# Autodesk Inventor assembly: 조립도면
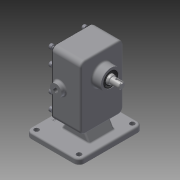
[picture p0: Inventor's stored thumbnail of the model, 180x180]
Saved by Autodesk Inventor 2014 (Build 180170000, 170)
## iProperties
Created: 2020-04
Part Number: 조립도면
Document SubType Name: Assembly
Designer: kh
Author: kh
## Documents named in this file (11)
- C:\Users\kh\Desktop\700407V1020\조립도면.iam
- C:\Users\kh\Desktop\700407V1020\본체.ipt
- C:\Users\kh\Desktop\700407V1020\개스킷.ipt
- C:\Users\kh\Desktop\700407V1020\메인축.ipt
- C:\Users\kh\Desktop\700407V1020\베어링부시.ipt
- C:\Users\kh\Desktop\700407V1020\볼트 M5.ipt
- C:\Users\kh\Desktop\700407V1020\서브축.ipt
- C:\Users\kh\Desktop\700407V1020\스퍼기어.ipt
- C:\Users\kh\Desktop\700407V1020\오일 실 16 28 7.ipt
- C:\Users\kh\Desktop\700407V1020\커버.ipt
- C:\Users\kh\Desktop\700407V1020\키 6 x 6 x 18.ipt
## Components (1 placed, 1 different names)
1. 개스킷:1
